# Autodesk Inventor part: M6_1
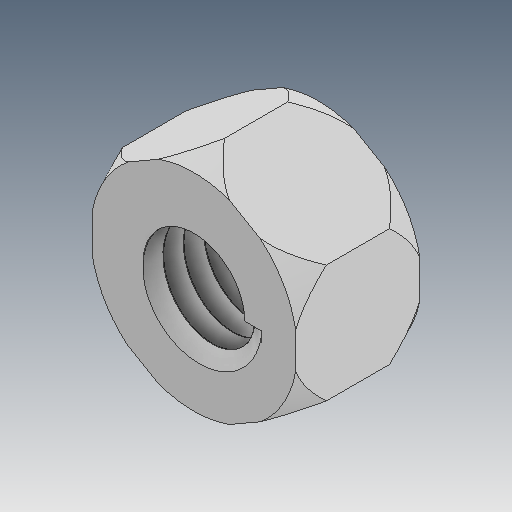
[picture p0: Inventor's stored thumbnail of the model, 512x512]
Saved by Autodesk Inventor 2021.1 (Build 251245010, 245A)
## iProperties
Created: 2019-05
Part Number: M6_1
Material: Ogólny
Document SubType Name: Modeling
Designer: user
Density: 1 g/cm^3
Appearance: Domyślna
Author: user
Revision Number: ÈÎºÎ
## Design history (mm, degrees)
feature "ÊäÈë1"
node "Bryła1"
